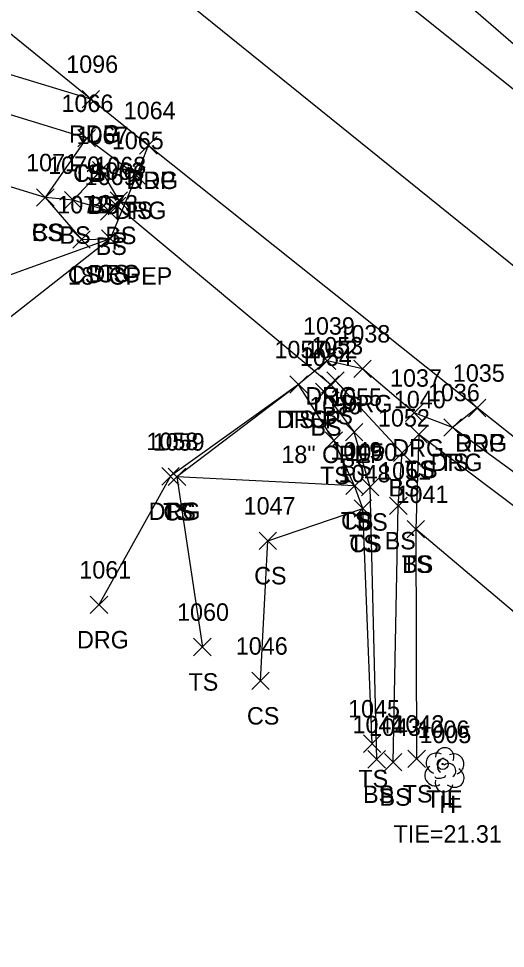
# Model space of a CAD drawing. Extents: x 1537342 to 1542195, y 163002 to 168596.
# Drawn here: x 1542043.7 to 1542099.6, y 163020.6 to 163127.1 of the extents above; entities that cross this region are included whole.
import ezdxf

# ---------------------------------------------------------------- set-up
doc = ezdxf.new("R2010")
doc.units = 0
for name, color, linetype in [('C_A', 7, 'Continuous'), ('C_C', 7, 'Continuous'), ('C_I', 7, 'Continuous'), ('CBP', 7, 'Continuous'), ('D_A', 7, 'Continuous'), ('D_C', 7, 'Continuous'), ('D_I', 7, 'Continuous'), ('D_TIC', 7, 'Continuous'), ('DCP', 7, 'Continuous'), ('L_A', 7, 'Continuous'), ('L_I', 7, 'Continuous'), ('L_TIC', 7, 'Continuous'), ('LELB', 7, 'Continuous'), ('LTD', 7, 'Continuous'), ('P_A', 7, 'Continuous'), ('P_I', 7, 'Continuous'), ('P_TIC', 7, 'Continuous'), ('PET', 7, 'Continuous'), ('PEU', 7, 'Continuous'), ('PRC', 7, 'Continuous'), ('R_A', 7, 'Continuous'), ('R_I', 7, 'Continuous'), ('R_TIC', 7, 'Continuous'), ('RDG', 7, 'Continuous')]:
    doc.layers.add(name, color=color, linetype=linetype)

msp = doc.modelspace()

# ---------------------------------------------------------------- linework, layer by layer
at = {"layer": 'CBP'}
for radius in [0.625, 0.0833]:
    msp.add_circle((1542092.38, 163041.68), radius, dxfattribs=at)
at = {"layer": 'D_TIC'}
for points in [[(1542054.02, 163104.59), (1542056.02, 163106.59)], [(1542056.02, 163104.59), (1542054.02, 163106.59)], [(1542078.49, 163084.15), (1542080.49, 163086.15)], [(1542080.49, 163084.15), (1542078.49, 163086.15)]]:
    msp.add_lwpolyline(points, dxfattribs=at)
at = {"layer": 'DCP'}
msp.add_lwpolyline([(1542079.49, 163085.15), (1542055.02, 163105.59)], dxfattribs=at)
at = {"layer": 'L_TIC'}
for points in [[(1542050.54, 163112.36), (1542052.54, 163114.36)], [(1542052.54, 163112.36), (1542050.54, 163114.36)], [(1542050.54, 163112.36), (1542052.54, 163114.36)], [(1542052.54, 163112.36), (1542050.54, 163114.36)], [(1542052.2, 163108.68), (1542054.2, 163110.68)], [(1542054.2, 163108.68), (1542052.2, 163110.68)], [(1542052.2, 163108.68), (1542054.2, 163110.68)], [(1542054.2, 163108.68), (1542052.2, 163110.68)], [(1542056.25, 163108.1), (1542058.25, 163110.1)], [(1542058.25, 163108.1), (1542056.25, 163110.1)], [(1542045.8, 163105.57), (1542047.8, 163107.57)], [(1542047.8, 163105.57), (1542045.8, 163107.57)], [(1542045.8, 163105.57), (1542047.8, 163107.57)], [(1542047.8, 163105.57), (1542045.8, 163107.57)], [(1542048.99, 163105.27), (1542050.99, 163107.27)], [(1542050.99, 163105.27), (1542048.99, 163107.27)], [(1542048.99, 163105.27), (1542050.99, 163107.27)], [(1542050.99, 163105.27), (1542048.99, 163107.27)], [(1542054.24, 163105.23), (1542056.24, 163107.23)], [(1542056.24, 163105.23), (1542054.24, 163107.23)], [(1542053.14, 163103.99), (1542055.14, 163105.99)], [(1542055.14, 163103.99), (1542053.14, 163105.99)], [(1542053.25, 163100.85), (1542055.25, 163102.85)], [(1542055.25, 163100.85), (1542053.25, 163102.85)], [(1542049.95, 163100.75), (1542051.95, 163102.75)], [(1542051.95, 163100.75), (1542049.95, 163102.75)], [(1542074.85, 163084.16), (1542076.85, 163086.16)], [(1542076.85, 163084.16), (1542074.85, 163086.16)], [(1542079.07, 163084.59), (1542081.07, 163086.59)], [(1542081.07, 163084.59), (1542079.07, 163086.59)], [(1542077.77, 163083.29), (1542079.77, 163085.29)], [(1542079.77, 163083.29), (1542077.77, 163085.29)], [(1542081.23, 163078.7), (1542083.23, 163080.7)], [(1542083.23, 163078.7), (1542081.23, 163080.7)], [(1542081.23, 163078.7), (1542083.23, 163080.7)], [(1542083.23, 163078.7), (1542081.23, 163080.7)], [(1542088.63, 163078.43), (1542090.63, 163080.43)], [(1542090.63, 163078.43), (1542088.63, 163080.43)], [(1542088.63, 163078.43), (1542090.63, 163080.43)], [(1542090.63, 163078.43), (1542088.63, 163080.43)], [(1542092.51, 163079.24), (1542094.51, 163081.24)], [(1542094.51, 163079.24), (1542092.51, 163081.24)], [(1542078.89, 163077.74), (1542080.89, 163079.74)], [(1542080.89, 163077.74), (1542078.89, 163079.74)], [(1542086.72, 163076.33), (1542088.72, 163078.33)], [(1542088.72, 163076.33), (1542086.72, 163078.33)], [(1542060.9, 163073.58), (1542062.9, 163075.58)], [(1542062.9, 163073.58), (1542060.9, 163075.58)], [(1542060.9, 163073.58), (1542062.9, 163075.58)], [(1542062.9, 163073.58), (1542060.9, 163075.58)], [(1542081.27, 163072.56), (1542083.27, 163074.56)], [(1542083.27, 163072.56), (1542081.27, 163074.56)], [(1542081.27, 163072.56), (1542083.27, 163074.56)], [(1542083.27, 163072.56), (1542081.27, 163074.56)], [(1542083.05, 163072.41), (1542085.05, 163074.41)], [(1542085.05, 163072.41), (1542083.05, 163074.41)], [(1542082.22, 163069.95), (1542084.22, 163071.95)], [(1542084.22, 163069.95), (1542082.22, 163071.95)], [(1542082.22, 163069.95), (1542084.22, 163071.95)], [(1542084.22, 163069.95), (1542082.22, 163071.95)], [(1542086.28, 163070.27), (1542088.28, 163072.27)], [(1542088.28, 163070.27), (1542086.28, 163072.27)], [(1542088.28, 163067.58), (1542090.28, 163069.58)], [(1542090.28, 163067.58), (1542088.28, 163069.58)], [(1542088.28, 163067.58), (1542090.28, 163069.58)], [(1542090.28, 163067.58), (1542088.28, 163069.58)], [(1542071.31, 163066.26), (1542073.31, 163068.26)], [(1542073.31, 163066.26), (1542071.31, 163068.26)], [(1542063.81, 163054.09), (1542065.81, 163056.09)], [(1542065.81, 163054.09), (1542063.81, 163056.09)], [(1542070.48, 163050.21), (1542072.48, 163052.21)], [(1542072.48, 163050.21), (1542070.48, 163052.21)], [(1542083.29, 163043.02), (1542085.29, 163045.02)], [(1542085.29, 163043.02), (1542083.29, 163045.02)], [(1542083.8, 163041.22), (1542085.8, 163043.22)], [(1542085.8, 163041.22), (1542083.8, 163043.22)], [(1542088.38, 163041.28), (1542090.38, 163043.28)], [(1542090.38, 163041.28), (1542088.38, 163043.28)], [(1542085.69, 163040.91), (1542087.69, 163042.91)], [(1542087.69, 163040.91), (1542085.69, 163042.91)]]:
    msp.add_lwpolyline(points, dxfattribs=at)
at = {"layer": 'LELB'}
for points in [[(1542183.12, 163055.05), (1542146.29, 163085.37), (1542113.65, 163112.77), (1542073.54, 163147.5), (1542044.28, 163168.18), (1542019.33, 163189.82), (1542014.69, 163194.08)], [(1542057.25, 163109.1), (1542051.54, 163113.36), (1542031.96, 163119.35), (1542019.61, 163119.84), (1542016.13, 163107.06), (1541999.95, 163096.16)], [(1542051.54, 163113.36), (1542046.8, 163106.57), (1542050.95, 163101.75), (1542054.25, 163101.85), (1542032.19, 163093.9), (1542014.23, 163087.23)], [(1542053.2, 163109.68), (1542055.24, 163106.23), (1542054.14, 163104.99), (1542049.99, 163106.27), (1542046.8, 163106.57), (1542028.7, 163112.12), (1542020.72, 163104.69), (1542009.94, 163090.62)], [(1542053.2, 163109.68), (1542049.99, 163106.27)], [(1542084.29, 163044.02), (1542083.22, 163070.95), (1542082.27, 163073.56), (1542079.89, 163078.74), (1542075.85, 163085.16), (1542061.9, 163074.58), (1542064.81, 163055.09)], [(1542086.69, 163041.91), (1542087.28, 163071.27), (1542087.72, 163077.33), (1542080.07, 163085.59), (1542078.77, 163084.29), (1542082.23, 163079.7)], [(1542084.8, 163042.22), (1542084.05, 163073.41), (1542082.23, 163079.7)], [(1542089.63, 163079.43), (1542089.28, 163068.58), (1542089.38, 163042.28)], [(1542162.42, 163026.75), (1542124.02, 163053.54), (1542089.63, 163079.43)], [(1542164.5, 163028.8), (1542125.79, 163056.7), (1542093.51, 163080.24)], [(1542082.27, 163073.56), (1542061.9, 163074.58)], [(1542071.48, 163051.21), (1542072.31, 163067.26), (1542083.22, 163070.95)], [(1542157.86, 163020.57), (1542118.09, 163044.29), (1542089.28, 163068.58)]]:
    msp.add_lwpolyline(points, dxfattribs=at)
at = {"layer": 'LTD'}
msp.add_line((1542092.55, 163041.08), (1542092.55, 163041.08), dxfattribs=at)
msp.add_line((1542092.55, 163041.08), (1542092.55, 163041.08), dxfattribs=at)
msp.add_arc((1542092.6, 163042.51), 1.05, 335.5272, 180.9563, dxfattribs=at)
for centre, major_axis, ratio, start_param, end_param in [((1542091.76, 163041.74), (1.21, -0.51), 0.895232, 1.570796, 4.712389), ((1542092.34, 163041.53), (-0.208, -0.792), 0.645439, 3.141593, 6.283185), ((1542093.59, 163041.66), (-1.14, -0.48), 0.949671, 1.570796, 4.712389), ((1542091.47, 163040.37), (0.58, -1.04), 0.959034, 3.141593, 6.283185), ((1542093.05, 163040.91), (-0.5, 0.667), 0.989748, 3.141593, 6.283185), ((1542093.55, 163040.24), (-1.09, 0.79), 0.841452, 1.570796, 4.712389), ((1542092.09, 163040.33), (-0.625, -0.083), 0.423636, 0, 3.141593), ((1542092.55, 163039.58), (0.26, 1.06), 0.942809, 1.570796, 4.712389)]:
    msp.add_ellipse(centre, major_axis=major_axis, ratio=ratio, start_param=start_param, end_param=end_param, dxfattribs=at)
at = {"layer": 'P_TIC'}
for points in [[(1542051.02, 163116.84), (1542053.02, 163118.84)], [(1542053.02, 163116.84), (1542051.02, 163118.84)], [(1542051.02, 163116.84), (1542053.02, 163118.84)], [(1542053.02, 163116.84), (1542051.02, 163118.84)], [(1542057.61, 163111.54), (1542059.61, 163113.54)], [(1542059.61, 163111.54), (1542057.61, 163113.54)], [(1542095.32, 163081.47), (1542097.32, 163083.47)], [(1542097.32, 163081.47), (1542095.32, 163083.47)]]:
    msp.add_lwpolyline(points, dxfattribs=at)
at = {"layer": 'PET'}
for points in [[(1542165.56, 163030.05), (1542126.67, 163058.36), (1542096.32, 163082.47), (1542058.61, 163112.54), (1542052.02, 163117.84), (1542010.73, 163151.35), (1541978.73, 163177.48), (1541958.58, 163193.33), (1541928.58, 163217.89), (1541894.65, 163244.61), (1541857.53, 163271.04), (1541839.6, 163283.45), (1541795.58, 163311.16), (1541814.19, 163318.82), (1541832.22, 163326.69)], [(1542182.46, 163052.97), (1542144.74, 163083.14), (1542111.59, 163110.07), (1542069.86, 163143.45), (1542042.93, 163166.04), (1542014.58, 163189.13), (1541996.52, 163203.32), (1541975.27, 163220.84), (1541953.96, 163238.23), (1541914.85, 163268.66), (1541894.39, 163285), (1541874.19, 163298.08), (1541854.83, 163311.47), (1541832.22, 163326.69)]]:
    msp.add_lwpolyline(points, dxfattribs=at)
at = {"layer": 'PEU'}
msp.add_lwpolyline([(1542052.02, 163117.84), (1542027.61, 163125.22), (1542015.69, 163126.52), (1542006.7, 163123.23), (1541994.86, 163108.85), (1541980.15, 163086.38)], dxfattribs=at)
at = {"layer": 'PRC'}
msp.add_lwpolyline([(1542174.18, 163041.84), (1542135.38, 163070.51), (1542102.15, 163097.42), (1542058.02, 163132.98), (1542032.76, 163153.88), (1541982.81, 163194.28), (1541947.35, 163222.57), (1541904.32, 163256.11), (1541874.29, 163278.53), (1541825.99, 163311), (1541814.19, 163318.82)], dxfattribs=at)
at = {"layer": 'R_TIC'}
for points in [[(1542057.61, 163111.54), (1542059.61, 163113.54)], [(1542059.61, 163111.54), (1542057.61, 163113.54)], [(1542056.25, 163108.1), (1542058.25, 163110.1)], [(1542058.25, 163108.1), (1542056.25, 163110.1)], [(1542053.25, 163100.85), (1542055.25, 163102.85)], [(1542055.25, 163100.85), (1542053.25, 163102.85)], [(1542078.13, 163086.86), (1542080.13, 163088.86)], [(1542080.13, 163086.86), (1542078.13, 163088.86)], [(1542082.18, 163085.96), (1542084.18, 163087.96)], [(1542084.18, 163085.96), (1542082.18, 163087.96)], [(1542074.85, 163084.16), (1542076.85, 163086.16)], [(1542076.85, 163084.16), (1542074.85, 163086.16)], [(1542088.11, 163080.9), (1542090.11, 163082.9)], [(1542090.11, 163080.9), (1542088.11, 163082.9)], [(1542095.32, 163081.47), (1542097.32, 163083.47)], [(1542097.32, 163081.47), (1542095.32, 163083.47)], [(1542092.51, 163079.24), (1542094.51, 163081.24)], [(1542094.51, 163079.24), (1542092.51, 163081.24)], [(1542060.16, 163073.64), (1542062.16, 163075.64)], [(1542062.16, 163073.64), (1542060.16, 163075.64)], [(1542051.95, 163058.93), (1542053.95, 163060.93)], [(1542053.95, 163058.93), (1542051.95, 163060.93)]]:
    msp.add_lwpolyline(points, dxfattribs=at)
at = {"layer": 'RDG'}
for points in [[(1542058.61, 163112.54), (1542057.25, 163109.1), (1542054.25, 163101.85), (1542039.05, 163089.97), (1542019.78, 163083.62)], [(1542096.32, 163082.47), (1542093.51, 163080.24), (1542089.11, 163081.9), (1542083.18, 163086.96), (1542079.13, 163087.86), (1542075.85, 163085.16), (1542061.16, 163074.64), (1542052.95, 163059.93)]]:
    msp.add_lwpolyline(points, dxfattribs=at)

# ---------------------------------------------------------------- texts
at = {"layer": 'C_A'}
msp.add_text('TIE', height=2, dxfattribs=at).set_placement((1542090.46, 163036.68))
at = {"layer": 'C_C'}
msp.add_text('TIE=21.31', height=2, dxfattribs=at).set_placement((1542086.74, 163032.68))
at = {"layer": 'C_I'}
msp.add_text('1006', height=2, dxfattribs=at).set_placement((1542089.48, 163044.68))
at = {"layer": 'D_A'}
for p in [(1542054.4, 163100.59), (1542078.87, 163080.15)]:
    msp.add_text('P', height=2, dxfattribs=at).set_placement(p)
at = {"layer": 'D_C'}
for p in [(1542049.4, 163096.59), (1542073.87, 163076.15)]:
    msp.add_text('18" CPEP', height=2, dxfattribs=at).set_placement(p)
at = {"layer": 'D_I'}
for s, p in [('1063', (1542052.2, 163108.59)), ('1062', (1542076.67, 163088.15))]:
    msp.add_text(s, height=2, dxfattribs=at).set_placement(p)
at = {"layer": 'L_A'}
for s, p in [('TS', (1542049.94, 163108.36)), ('CS', (1542049.98, 163108.36)), ('BS', (1542051.64, 163104.68)), ('BS', (1542051.64, 163104.68)), ('TS', (1542055.66, 163104.1)), ('CS', (1542045.24, 163101.57)), ('BS', (1542045.24, 163101.57)), ('BS', (1542048.43, 163101.27)), ('BS', (1542048.43, 163101.27)), ('BS', (1542053.68, 163101.23)), ('BS', (1542052.58, 163099.99)), ('CS', (1542049.39, 163096.75)), ('CS', (1542052.69, 163096.85)), ('BS', (1542078.51, 163080.59)), ('TS', (1542074.26, 163080.16)), ('BS', (1542077.21, 163079.29)), ('TS', (1542091.92, 163075.24)), ('BS', (1542080.67, 163074.7)), ('BS', (1542080.67, 163074.7)), ('TS', (1542088.04, 163074.43)), ('CS', (1542088.07, 163074.43)), ('TS', (1542078.3, 163073.74)), ('BS', (1542086.16, 163072.33)), ('TS', (1542060.31, 163069.58)), ('CS', (1542060.34, 163069.58)), ('TS', (1542080.67, 163068.56)), ('CS', (1542080.71, 163068.56)), ('BS', (1542082.5, 163068.41)), ('TS', (1542081.63, 163065.95)), ('CS', (1542081.66, 163065.95)), ('BS', (1542085.72, 163066.27)), ('TS', (1542087.69, 163063.58)), ('BS', (1542087.72, 163063.58)), ('CS', (1542070.75, 163062.26)), ('TS', (1542063.22, 163050.09)), ('CS', (1542069.92, 163046.21)), ('TS', (1542082.7, 163039.02)), ('BS', (1542083.24, 163037.22)), ('BS', (1542085.13, 163036.91)), ('TS', (1542087.79, 163037.28)), ('H', (1542091.98, 163036.08))]:
    msp.add_text(s, height=2, dxfattribs=at).set_placement(p)
at = {"layer": 'L_I'}
for s, p in [('1066', (1542048.66, 163116.36)), ('1066', (1542048.66, 163116.36)), ('1067', (1542050.38, 163112.68)), ('1067', (1542050.38, 163112.68)), ('1065', (1542054.43, 163112.1)), ('1071', (1542044.6, 163109.57)), ('1071', (1542044.6, 163109.57)), ('1070', (1542047.13, 163109.27)), ('1070', (1542047.13, 163109.27)), ('1068', (1542052.42, 163109.23)), ('1069', (1542051.31, 163107.99)), ('1072', (1542048.17, 163104.75)), ('1073', (1542051.48, 163104.85)), ('1057', (1542073.08, 163088.16)), ('1053', (1542077.3, 163088.59)), ('1054', (1542076, 163087.29)), ('1055', (1542079.46, 163082.7)), ('1055', (1542079.46, 163082.7)), ('1036', (1542090.68, 163083.24)), ('1056', (1542077.07, 163081.74)), ('1040', (1542086.77, 163082.43)), ('1040', (1542086.77, 163082.43)), ('1052', (1542084.95, 163080.33)), ('1059', (1542059.12, 163077.58)), ('1059', (1542059.12, 163077.58)), ('1049', (1542079.49, 163076.56)), ('1049', (1542079.49, 163076.56)), ('1050', (1542081.2, 163076.41)), ('1051', (1542085.08, 163074.27)), ('1048', (1542080.44, 163073.95)), ('1048', (1542080.44, 163073.95)), ('1041', (1542087.08, 163071.58)), ('1041', (1542087.08, 163071.58)), ('1047', (1542069.54, 163070.26)), ('1060', (1542061.91, 163058.09)), ('1046', (1542068.65, 163054.21)), ('1045', (1542081.52, 163047.02)), ('1044', (1542082.03, 163045.22)), ('1043', (1542083.92, 163044.91)), ('1042', (1542086.61, 163045.28)), ('1005', (1542089.7, 163044.08))]:
    msp.add_text(s, height=2, dxfattribs=at).set_placement(p)
at = {"layer": 'P_A'}
for s, p in [('RDG', (1542049.51, 163112.84)), ('RDP', (1542049.51, 163112.84)), ('RDP', (1542056.1, 163107.54)), ('RDP', (1542093.8, 163077.47))]:
    msp.add_text(s, height=2, dxfattribs=at).set_placement(p)
at = {"layer": 'P_I'}
for s, p in [('1096', (1542049.2, 163120.84)), ('1096', (1542049.2, 163120.84)), ('1064', (1542055.79, 163115.54)), ('1035', (1542093.54, 163085.47))]:
    msp.add_text(s, height=2, dxfattribs=at).set_placement(p)
at = {"layer": 'R_A'}
for p in [(1542056.1, 163107.54), (1542054.73, 163104.1), (1542051.74, 163096.85), (1542076.61, 163082.86), (1542080.67, 163081.96), (1542073.34, 163080.16), (1542093.8, 163077.47), (1542086.59, 163076.9), (1542090.99, 163075.24), (1542058.65, 163069.64), (1542050.44, 163054.93)]:
    msp.add_text('DRG', height=2, dxfattribs=at).set_placement(p)
at = {"layer": 'R_I'}
for s, p in [('1064', (1542055.79, 163115.54)), ('1065', (1542054.43, 163112.1)), ('1073', (1542051.48, 163104.85)), ('1039', (1542076.35, 163090.86)), ('1038', (1542080.41, 163089.96)), ('1057', (1542073.08, 163088.16)), ('1037', (1542086.33, 163084.9)), ('1035', (1542093.54, 163085.47)), ('1036', (1542090.68, 163083.24)), ('1058', (1542058.39, 163077.64)), ('1061', (1542050.7, 163062.93))]:
    msp.add_text(s, height=2, dxfattribs=at).set_placement(p)

doc.saveas('drawing.dxf')
